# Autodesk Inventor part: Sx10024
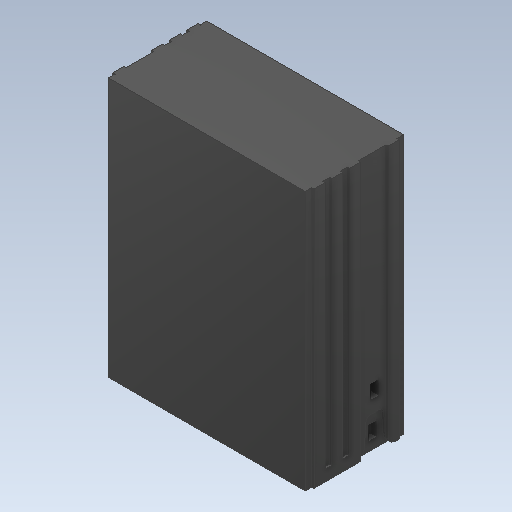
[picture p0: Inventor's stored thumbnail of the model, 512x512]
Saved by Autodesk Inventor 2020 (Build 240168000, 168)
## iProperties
Created: 2021-02
Part Number: Sx10024
Material: Generico
Document SubType Name: Modeling
Designer: zambolin
Density: 1 g/cm^3
Appearance: Default
Author: zambolin
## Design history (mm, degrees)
feature "Solido2"
node "Solido1"
